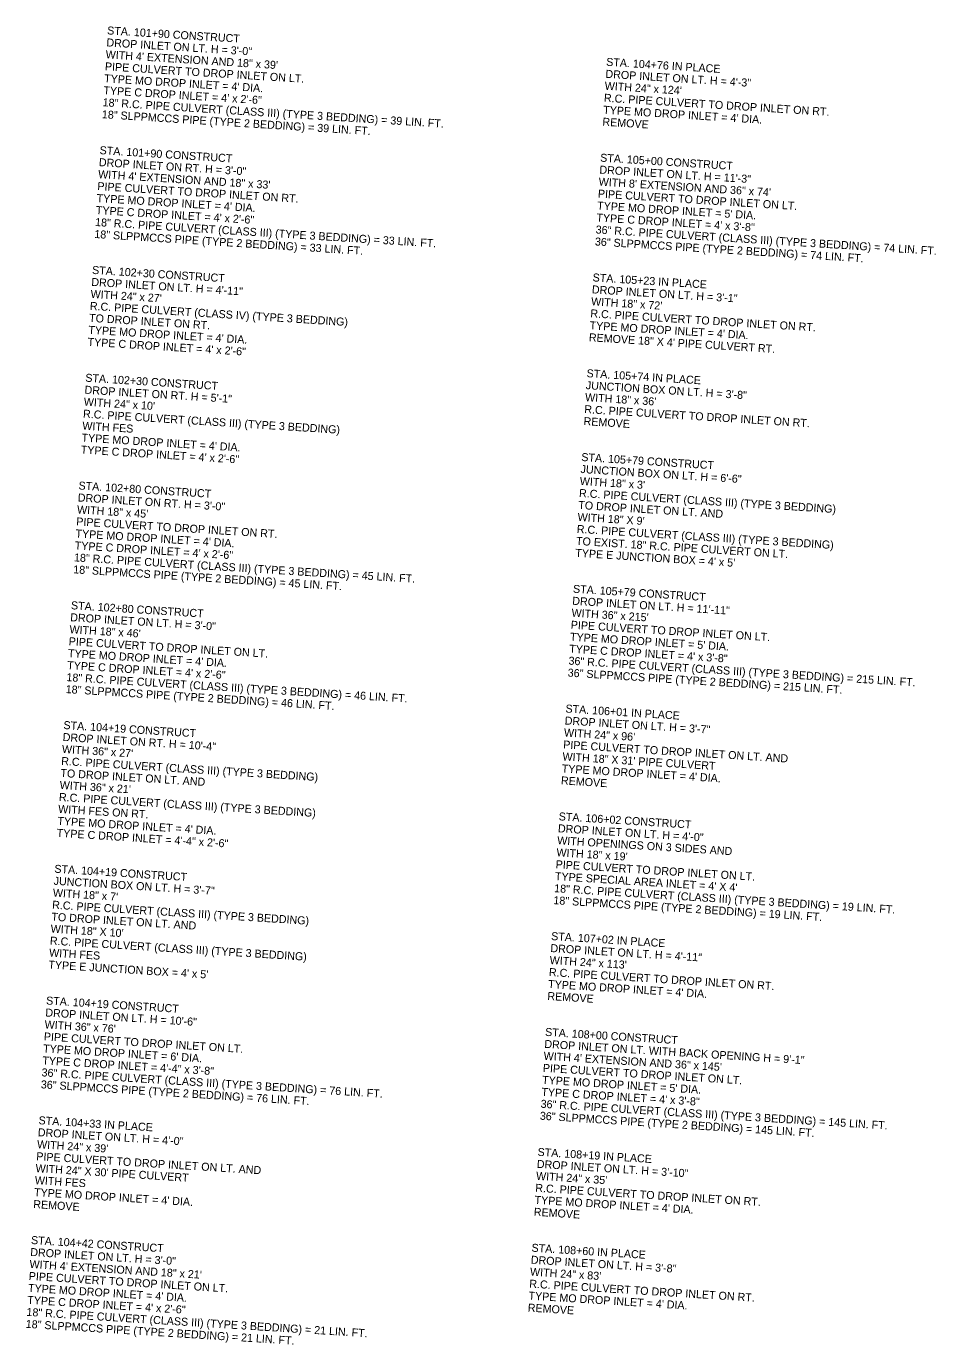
# Model space of a CAD drawing. Extents: x 660731 to 669183, y 641696 to 736523.
# Drawn here: x 660731 to 661413, y 641829 to 642818 of the extents above; entities that cross this region are included whole.
import ezdxf

# ---------------------------------------------------------------- set-up
doc = ezdxf.new("R2010")
doc.units = 0
doc.layers.add('T_Indications', color=7, linetype='Continuous')

msp = doc.modelspace()

# ---------------------------------------------------------------- texts
at = {"layer": 'T_Indications'}
for s, p in [('STA. 101+90 CONSTRUCT', (660791.59, 642811.96)), ('DROP INLET ON LT. H = 3\'-0"', (660791.03, 642802.98)), ('WITH 4\' EXTENSION AND 18" x 39\'', (660790.46, 642794)), ('PIPE CULVERT TO DROP INLET ON LT.', (660789.9, 642785.01)), ('STA. 104+76 IN PLACE', (661165.85, 642788.4)), ("TYPE MO DROP INLET = 4' DIA.", (660789.33, 642776.03)), ('DROP INLET ON LT. H = 4\'-3"', (661165.29, 642779.42)), ('TYPE C DROP INLET = 4\' x 2\'-6"', (660788.77, 642767.05)), ('WITH 24" x 124\'', (661164.72, 642770.44)), ('18" R.C. PIPE CULVERT (CLASS III) (TYPE 3 BEDDING) = 39 LIN. FT.', (660788.2, 642758.07)), ("TYPE MO DROP INLET = 4' DIA.", (661163.59, 642752.47)), ('R.C. PIPE CULVERT TO DROP INLET ON RT.', (661164.16, 642761.45)), ('18" SLPPMCCS PIPE (TYPE 2 BEDDING) = 39 LIN. FT.', (660787.64, 642749.09)), ('REMOVE', (661163.03, 642743.49)), ('STA. 101+90 CONSTRUCT', (660785.94, 642722.14)), ('DROP INLET ON RT. H = 3\'-0"', (660785.37, 642713.16)), ('STA. 105+00 CONSTRUCT', (661161.33, 642716.54)), ('WITH 4\' EXTENSION AND 18" x 33\'', (660784.81, 642704.17)), ('DROP INLET ON LT. H = 11\'-3"', (661160.76, 642707.56)), ('PIPE CULVERT TO DROP INLET ON RT.', (660784.24, 642695.19)), ('WITH 8\' EXTENSION AND 36" x 74\'', (661160.2, 642698.58)), ("TYPE MO DROP INLET = 4' DIA.", (660783.68, 642686.21)), ('PIPE CULVERT TO DROP INLET ON LT.', (661159.63, 642689.6)), ('TYPE C DROP INLET = 4\' x 2\'-6"', (660783.11, 642677.23)), ("TYPE MO DROP INLET = 5' DIA.", (661159.07, 642680.61)), ('18" R.C. PIPE CULVERT (CLASS III) (TYPE 3 BEDDING) = 33 LIN. FT.', (660782.55, 642668.25)), ('TYPE C DROP INLET = 4\' x 3\'-8"', (661158.5, 642671.63)), ('18" SLPPMCCS PIPE (TYPE 2 BEDDING) = 33 LIN. FT.', (660781.98, 642659.26)), ('36" SLPPMCCS PIPE (TYPE 2 BEDDING) = 74 LIN. FT.', (661157.37, 642653.67)), ('36" R.C. PIPE CULVERT (CLASS III) (TYPE 3 BEDDING) = 74 LIN. FT.', (661157.94, 642662.65)), ('DROP INLET ON LT. H = 4\'-11"', (660779.72, 642623.33)), ('STA. 102+30 CONSTRUCT', (660780.28, 642632.32)), ('STA. 105+23 IN PLACE', (661155.67, 642626.72)), ('WITH 24" x 27\'', (660779.15, 642614.35)), ('DROP INLET ON LT. H = 3\'-1"', (661155.11, 642617.74)), ('R.C. PIPE CULVERT (CLASS IV) (TYPE 3 BEDDING)', (660778.59, 642605.37)), ('WITH 18" x 72\'', (661154.54, 642608.76)), ('TO DROP INLET ON RT.', (660778.02, 642596.39)), ('R.C. PIPE CULVERT TO DROP INLET ON RT.', (661153.98, 642599.77)), ("TYPE MO DROP INLET = 4' DIA.", (660777.46, 642587.41)), ("TYPE MO DROP INLET = 4' DIA.", (661153.41, 642590.79)), ('TYPE C DROP INLET = 4\' x 2\'-6"', (660776.89, 642578.42)), ('REMOVE 18" X 4\' PIPE CULVERT RT.', (661152.85, 642581.81)), ('STA. 105+74 IN PLACE', (661151.15, 642554.86)), ('STA. 102+30 CONSTRUCT', (660775.2, 642551.48)), ('JUNCTION BOX ON LT. H = 3\'-8"', (661150.59, 642545.88)), ('DROP INLET ON RT. H = 5\'-1"', (660774.63, 642542.49)), ('WITH 18" x 36\'', (661150.02, 642536.9)), ('R.C. PIPE CULVERT (CLASS III) (TYPE 3 BEDDING)', (660773.5, 642524.53)), ('WITH 24" x 10\'', (660774.06, 642533.51)), ('R.C. PIPE CULVERT TO DROP INLET ON RT.', (661149.45, 642527.92)), ('WITH FES', (660772.93, 642515.55)), ('REMOVE', (661148.89, 642518.93)), ("TYPE MO DROP INLET = 4' DIA.", (660772.37, 642506.57)), ('TYPE C DROP INLET = 4\' x 2\'-6"', (660771.8, 642497.58)), ('STA. 105+79 CONSTRUCT', (661147.19, 642491.99)), ('JUNCTION BOX ON LT. H = 6\'-6"', (661146.63, 642483.01)), ('STA. 102+80 CONSTRUCT', (660770.11, 642470.64)), ('R.C. PIPE CULVERT (CLASS III) (TYPE 3 BEDDING)', (661145.5, 642465.04)), ('WITH 18" x 3\'', (661146.06, 642474.02)), ('DROP INLET ON RT. H = 3\'-0"', (660769.54, 642461.65)), ('TO DROP INLET ON LT. AND', (661144.93, 642456.06)), ('WITH 18" x 45\'', (660768.98, 642452.67)), ('WITH 18" X 9\'', (661144.37, 642447.08)), ('PIPE CULVERT TO DROP INLET ON RT.', (660768.41, 642443.69)), ('R.C. PIPE CULVERT (CLASS III) (TYPE 3 BEDDING)', (661143.8, 642438.09)), ('TYPE C DROP INLET = 4\' x 2\'-6"', (660767.28, 642425.73)), ("TYPE MO DROP INLET = 4' DIA.", (660767.84, 642434.71)), ('TO EXIST. 18" R.C. PIPE CULVERT ON LT.', (661143.23, 642429.11)), ('18" R.C. PIPE CULVERT (CLASS III) (TYPE 3 BEDDING) = 45 LIN. FT.', (660766.71, 642416.74)), ("TYPE E JUNCTION BOX = 4' x 5'", (661142.67, 642420.13)), ('18" SLPPMCCS PIPE (TYPE 2 BEDDING) = 45 LIN. FT.', (660766.15, 642407.76)), ('STA. 105+79 CONSTRUCT', (661140.97, 642393.18)), ('STA. 102+80 CONSTRUCT', (660764.45, 642380.81)), ('DROP INLET ON LT. H = 11\'-11"', (661140.41, 642384.2)), ('DROP INLET ON LT. H = 3\'-0"', (660763.89, 642371.83)), ('PIPE CULVERT TO DROP INLET ON LT.', (661139.28, 642366.24)), ('WITH 36" x 215\'', (661139.84, 642375.22)), ('WITH 18" x 46\'', (660763.32, 642362.85)), ("TYPE MO DROP INLET = 5' DIA.", (661138.71, 642357.25)), ('PIPE CULVERT TO DROP INLET ON LT.', (660762.76, 642353.87)), ('TYPE C DROP INLET = 4\' x 3\'-8"', (661138.15, 642348.27)), ("TYPE MO DROP INLET = 4' DIA.", (660762.19, 642344.89)), ('36" R.C. PIPE CULVERT (CLASS III) (TYPE 3 BEDDING) = 215 LIN. FT.', (661137.58, 642339.29)), ('18" R.C. PIPE CULVERT (CLASS III) (TYPE 3 BEDDING) = 46 LIN. FT.', (660761.06, 642326.92)), ('TYPE C DROP INLET = 4\' x 2\'-6"', (660761.62, 642335.9)), ('36" SLPPMCCS PIPE (TYPE 2 BEDDING) = 215 LIN. FT.', (661137.01, 642330.31)), ('18" SLPPMCCS PIPE (TYPE 2 BEDDING) = 46 LIN. FT.', (660760.49, 642317.94)), ('STA. 106+01 IN PLACE', (661135.32, 642303.36)), ('STA. 104+19 CONSTRUCT', (660758.8, 642290.99)), ('DROP INLET ON LT. H = 3\'-7"', (661134.75, 642294.38)), ('DROP INLET ON RT. H = 10\'-4"', (660758.23, 642282.01)), ('WITH 24" x 96\'', (661134.19, 642285.4)), ('WITH 36" x 27\'', (660757.67, 642273.03)), ('WITH 18" X 31\' PIPE CULVERT', (661133.06, 642267.43)), ('PIPE CULVERT TO DROP INLET ON LT. AND', (661133.62, 642276.41)), ('R.C. PIPE CULVERT (CLASS III) (TYPE 3 BEDDING)', (660757.1, 642264.05)), ("TYPE MO DROP INLET = 4' DIA.", (661132.49, 642258.45)), ('TO DROP INLET ON LT. AND', (660756.54, 642255.06)), ('REMOVE', (661131.93, 642249.47)), ('WITH 36" x 21\'', (660755.97, 642246.08)), ('WITH FES ON RT.', (660754.84, 642228.12)), ('R.C. PIPE CULVERT (CLASS III) (TYPE 3 BEDDING)', (660755.4, 642237.1)), ("TYPE MO DROP INLET = 4' DIA.", (660754.27, 642219.13)), ('STA. 106+02 CONSTRUCT', (661130.23, 642222.52)), ('TYPE C DROP INLET = 4\'-4" x 2\'-6"', (660753.71, 642210.15)), ('DROP INLET ON LT. H = 4\'-0"', (661129.66, 642213.54)), ('WITH OPENINGS ON 3 SIDES AND', (661129.1, 642204.56)), ('WITH 18" x 19\'', (661128.53, 642195.57)), ('STA. 104+19 CONSTRUCT', (660752.01, 642183.21)), ('PIPE CULVERT TO DROP INLET ON LT.', (661127.97, 642186.59)), ('JUNCTION BOX ON LT. H = 3\'-7"', (660751.45, 642174.22)), ('18" R.C. PIPE CULVERT (CLASS III) (TYPE 3 BEDDING) = 19 LIN. FT.', (661126.84, 642168.63)), ("TYPE SPECIAL AREA INLET = 4' X 4'", (661127.4, 642177.61)), ('WITH 18" x 7\'', (660750.88, 642165.24)), ('18" SLPPMCCS PIPE (TYPE 2 BEDDING) = 19 LIN. FT.', (661126.27, 642159.65)), ('R.C. PIPE CULVERT (CLASS III) (TYPE 3 BEDDING)', (660750.32, 642156.26)), ('TO DROP INLET ON LT. AND', (660749.75, 642147.28)), ('R.C. PIPE CULVERT (CLASS III) (TYPE 3 BEDDING)', (660748.62, 642129.31)), ('WITH 18" X 10\'', (660749.18, 642138.29)), ('STA. 107+02 IN PLACE', (661124.57, 642132.7)), ('WITH FES', (660748.05, 642120.33)), ('DROP INLET ON LT. H = 4\'-11"', (661124.01, 642123.72)), ("TYPE E JUNCTION BOX = 4' x 5'", (660747.49, 642111.35)), ('WITH 24" x 113\'', (661123.44, 642114.73)), ('R.C. PIPE CULVERT TO DROP INLET ON RT.', (661122.88, 642105.75)), ("TYPE MO DROP INLET = 4' DIA.", (661122.31, 642096.77)), ('STA. 104+19 CONSTRUCT', (660745.79, 642084.4)), ('REMOVE', (661121.75, 642087.79)), ('DROP INLET ON LT. H = 10\'-6"', (660745.23, 642075.42)), ('WITH 36" x 76\'', (660744.66, 642066.44)), ('STA. 108+00 CONSTRUCT', (661120.05, 642060.84)), ('PIPE CULVERT TO DROP INLET ON LT.', (660744.1, 642057.45)), ('DROP INLET ON LT. WITH BACK OPENING H = 9\'-1"', (661119.49, 642051.86)), ("TYPE MO DROP INLET = 6' DIA.", (660743.53, 642048.47)), ('WITH 4\' EXTENSION AND 36" x 145\'', (661118.92, 642042.88)), ('36" R.C. PIPE CULVERT (CLASS III) (TYPE 3 BEDDING) = 76 LIN. FT.', (660742.4, 642030.51)), ('TYPE C DROP INLET = 4\'-4" x 3\'-8"', (660742.96, 642039.49)), ('PIPE CULVERT TO DROP INLET ON LT.', (661118.35, 642033.89)), ('36" SLPPMCCS PIPE (TYPE 2 BEDDING) = 76 LIN. FT.', (660741.83, 642021.53)), ("TYPE MO DROP INLET = 5' DIA.", (661117.79, 642024.91)), ('TYPE C DROP INLET = 4\' x 3\'-8"', (661117.22, 642015.93)), ('36" R.C. PIPE CULVERT (CLASS III) (TYPE 3 BEDDING) = 145 LIN. FT.', (661116.66, 642006.95)), ('STA. 104+33 IN PLACE', (660740.14, 641994.58)), ('36" SLPPMCCS PIPE (TYPE 2 BEDDING) = 145 LIN. FT.', (661116.09, 641997.97)), ('DROP INLET ON LT. H = 4\'-0"', (660739.57, 641985.6)), ('WITH 24" x 39\'', (660739.01, 641976.61)), ('STA. 108+19 IN PLACE', (661114.39, 641970.85)), ('PIPE CULVERT TO DROP INLET ON LT. AND ', (660738.44, 641967.63)), ('DROP INLET ON LT. H = 3\'-10"', (661113.82, 641961.87)), ('WITH 24" X 30\' PIPE CULVERT', (660737.88, 641958.65)), ('WITH 24" x 35\'', (661113.26, 641952.89)), ('WITH FES', (660737.31, 641949.67)), ('R.C. PIPE CULVERT TO DROP INLET ON RT.', (661112.69, 641943.91)), ('REMOVE', (660736.18, 641931.7)), ("TYPE MO DROP INLET = 4' DIA.", (660736.74, 641940.69)), ("TYPE MO DROP INLET = 4' DIA.", (661112.12, 641934.92)), ('REMOVE', (661111.56, 641925.94)), ('STA. 104+42 CONSTRUCT', (660734.48, 641904.76)), ('DROP INLET ON LT. H = 3\'-0"', (660733.92, 641895.77)), ('STA. 108+60 IN PLACE', (661109.86, 641899)), ('WITH 4\' EXTENSION AND 18" x 21\'', (660733.35, 641886.79)), ('DROP INLET ON LT. H = 3\'-8"', (661109.3, 641890.01)), ('PIPE CULVERT TO DROP INLET ON LT.', (660732.79, 641877.81)), ('R.C. PIPE CULVERT TO DROP INLET ON RT.', (661108.17, 641872.05)), ('WITH 24" x 83\'', (661108.73, 641881.03)), ("TYPE MO DROP INLET = 4' DIA.", (660732.22, 641868.83)), ("TYPE MO DROP INLET = 4' DIA.", (661107.6, 641863.07)), ('TYPE C DROP INLET = 4\' x 2\'-6"', (660731.66, 641859.85)), ('REMOVE', (661107.04, 641854.08)), ('18" R.C. PIPE CULVERT (CLASS III) (TYPE 3 BEDDING) = 21 LIN. FT.', (660731.09, 641850.86)), ('18" SLPPMCCS PIPE (TYPE 2 BEDDING) = 21 LIN. FT.', (660730.52, 641841.88))]:
    msp.add_text(s, height=6, rotation=356.39787, dxfattribs=at).set_placement(p)

doc.saveas('drawing.dxf')
